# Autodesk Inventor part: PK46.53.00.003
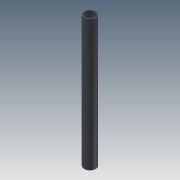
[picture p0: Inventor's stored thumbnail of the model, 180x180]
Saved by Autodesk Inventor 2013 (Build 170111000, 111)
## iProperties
Created: 2005-03
Part Number: PK46.53.00.003
Material: Steel, Mild
Document SubType Name: Modeling
Designer: HKostja
Manufacturer: Standard
Standards Organization: Custom
Density: 7.86 g/cm^3
Mass: 2270.61 g
Surface Area: 1660.98 cm^2
Volume: 288.881 cm^3
Author: HKostja
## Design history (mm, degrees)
sketch "Эскиз1"
  geometry: C1 r 25 at (0, 0); C2 r 21.5 at (0, 0)
  constraints: 2 centre point, 1 coincident, 1 other
  dimensions: "d0" = 3.5 radial gap between concentric circles of C1 C2; "d1" = 50 diameter of C1
extrude "Выдавливание2" new body sketch "Эскиз1" distance "d8" = 565; taper "d9" = 0 deg
body "Solid1"
